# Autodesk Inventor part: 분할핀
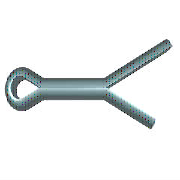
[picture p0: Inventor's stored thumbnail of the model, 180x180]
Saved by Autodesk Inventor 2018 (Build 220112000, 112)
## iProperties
IsCustomPart: 1
Created: 2012-02
Part Number: 분할핀
Material: 강철
Description: 분할 핀
Document SubType Name: Modeling
Standard: ISO 1234
Designer: mdu-01
Standard Revision: Second edition 1997-11-01
Standards Organization: ISO
Language: ko-KR
Size Designation: 2 x 14
Categories: <MemberInstance><Categories><Category DisplayName="조임쇠" InternalName="e4da775c-781d-43d5-af7c-5136215cf5a6" Mnemonic="FSTN"><Category DisplayName="핀" InternalNa
Density: 7.85 g/cm^3
Appearance: 파란색 - 벽 페인트 - 광택
Author: mdu-01
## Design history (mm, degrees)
sketch "스케치1"
  geometry: L1 (0, 0.9)-(8, 0.9); L2 (0, -0.9)-(8, -0.9); L3 (8, 0.9)-(14, 3.199); L4 (14, 3.199)-(14.301, 2.414); L5 (14.301, 2.414)-(8, 0); L6 (8, 0)-(16.801, -3.372); L7 (16.801, -3.372)-(16.5, -4.157); L8 (16.5, -4.157)-(8, -0.9); L9 (0, 0)-(-1.832, -0.821); L10 (0, 0)-(-1.832, 0.821); L11 (0, 0.9)-(0, -0.9); L12 (0, 0.9)-(-1.384, 1.604); L13 (0, -0.9)-(-1.384, -1.604); L14 (-4, 0)-(8, 0); L15 (8, 0.9)-(8, -0.9); A1 r 1.8 centre (-2.2, 0) between (-1.384, 1.604) and (-1.384, -1.604); A2 r 0.9 centre (-2.2, 0) between (-1.832, 0.821) and (-1.832, -0.821); 1 further point
  constraints: 30 end point, 5 point on circle, 4 parallel, 4 perpendicular, 4 point on line, 4 tangent, 2 centre point, 2 midpoint, 1 coincident, 1 horizontal
  dimensions: "d0" = 8 distance of L1.start L1.end (= MSIAB); "d1" = 14 horizontal distance of L1.start L3.end (= SNLG); "d2" = 159.037 deg angle of L1 L3; "d3" = 159.037 deg angle of L2 L8; "d4" = 2.5 horizontal distance of L3.end L7.end (= LGDIF); "d5" = 0.9 radius of A2 (= -0.5 x SNND1 + 0.5 x KBR); "d6" = 1.8 radius of A1 (= 0.5 x KBR); "d7" = 0.9 distance from line of L1 L9.start (= 0.5 x SNND1); "d8" = 0.9 distance between parallel lines of L2 L14 (= 0.5 x SNND1); "d9" = 2.2 distance from line of L11 A1.centre (= KOL - 0.5 x KBR)
extrude "본체" new body sketch "스케치1" stored distance "d10" = 1.8 (= SNND1); taper "d11" = 0 deg
workaxis "Work Axis1"
workplane "Work Plane1"
body "Solid1"
fillet "모깎기" dims "d12" = 0.72 (= 0.4 x SNND1)
node "작업 평면2"
other parameters: "SNND" = 2 [user parameter], "SNLG" = 14 [user parameter; used in 1 equation term], "SNND1" = 1.8 [user parameter; used in 5 equation terms], "KBR" = 3.6 [user parameter; used in 3 equation terms], "KOL" = 4 [user parameter; used in 1 equation term], "LGDIF" = 2.5 [user parameter; used in 1 equation term], "MSIAB" = 8 [user parameter; used in 1 equation term], "d15" = 0, "d16" = 0, "d17" = 0, "NNDMAX" = 9 [user parameter], "DSH" = 4 [user parameter], "NNDMIN" = 7 [user parameter]
